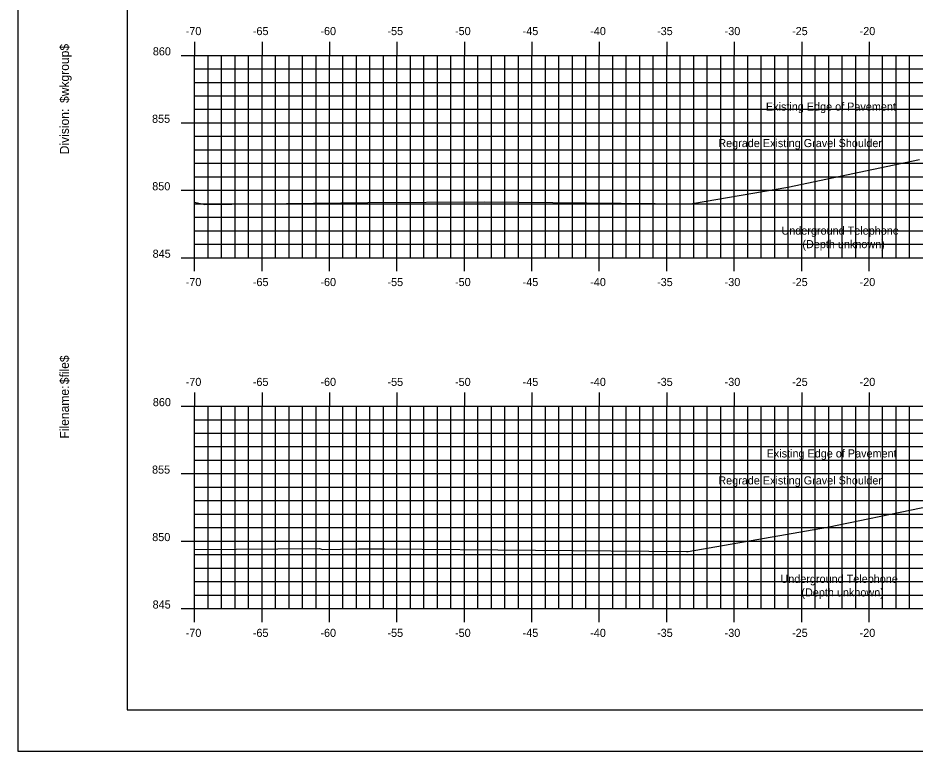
# Model space of a CAD drawing. Extents: x 2193811 to 2194294, y 863888 to 863998.
# Drawn here: x 2193950.1 to 2194016.6, y 863888.4 to 863942.7 of the extents above; entities that cross this region are included whole.
import ezdxf

# ---------------------------------------------------------------- set-up
doc = ezdxf.new("R2010")
doc.units = 0
for name, color, linetype in [('ANNOTATION', 7, 'Continuous'), ('BORDER', 7, 'Continuous'), ('H_V ANNOTATION', 7, 'Continuous'), ('MAJOR', 7, 'Continuous'), ('MINOR', 7, 'Continuous'), ('PLOT BOUNDARY', 7, 'Continuous'), ('S_Roadway_Centerline', 7, 'Continuous')]:
    doc.layers.add(name, color=color, linetype=linetype)

msp = doc.modelspace()

# ---------------------------------------------------------------- linework, layer by layer
at = {"layer": 'BORDER'}
msp.add_lwpolyline([(2193958.23, 863891.446), (2194118.23, 863891.446), (2194118.23, 863996.446), (2193958.23, 863996.446)], close=True, dxfattribs=at)
at = {"layer": 'MAJOR'}
for p, q in [((2193963.23, 863940.948), (2193963.23, 863939.946)), ((2193968.23, 863940.948), (2193968.23, 863939.946)), ((2193973.23, 863940.948), (2193973.23, 863939.946)), ((2193978.23, 863940.948), (2193978.23, 863939.946)), ((2193983.23, 863940.948), (2193983.23, 863939.946)), ((2193988.23, 863940.948), (2193988.23, 863939.946)), ((2193993.23, 863940.948), (2193993.23, 863939.946)), ((2193998.23, 863940.948), (2193998.23, 863939.946)), ((2194003.23, 863940.948), (2194003.23, 863939.946)), ((2194008.23, 863940.948), (2194008.23, 863939.946)), ((2194013.23, 863940.948), (2194013.23, 863939.946)), ((2193962.228, 863939.946), (2193963.23, 863939.946)), ((2193963.23, 863939.946), (2194103.23, 863939.946)), ((2193963.23, 863939.946), (2194103.23, 863939.946)), ((2193963.23, 863924.946), (2193963.23, 863939.946)), ((2193963.23, 863924.946), (2193963.23, 863939.946)), ((2193968.23, 863924.946), (2193968.23, 863939.946)), ((2193973.23, 863924.946), (2193973.23, 863939.946)), ((2193978.23, 863924.946), (2193978.23, 863939.946)), ((2193983.23, 863924.946), (2193983.23, 863939.946)), ((2193988.23, 863924.946), (2193988.23, 863939.946)), ((2193993.23, 863924.946), (2193993.23, 863939.946)), ((2193998.23, 863924.946), (2193998.23, 863939.946)), ((2194003.23, 863924.946), (2194003.23, 863939.946)), ((2194008.23, 863924.946), (2194008.23, 863939.946)), ((2194013.23, 863924.946), (2194013.23, 863939.946)), ((2193962.228, 863934.946), (2193963.23, 863934.946)), ((2193963.23, 863934.946), (2194103.23, 863934.946)), ((2193962.228, 863929.946), (2193963.23, 863929.946)), ((2193963.23, 863929.946), (2194103.23, 863929.946)), ((2193962.228, 863924.946), (2193963.23, 863924.946)), ((2193963.23, 863924.946), (2194103.23, 863924.946)), ((2193963.23, 863923.944), (2193963.23, 863924.946)), ((2193968.23, 863923.944), (2193968.23, 863924.946)), ((2193973.23, 863923.944), (2193973.23, 863924.946)), ((2193978.23, 863923.944), (2193978.23, 863924.946)), ((2193983.23, 863923.944), (2193983.23, 863924.946)), ((2193988.23, 863923.944), (2193988.23, 863924.946)), ((2193993.23, 863923.944), (2193993.23, 863924.946)), ((2193998.23, 863923.944), (2193998.23, 863924.946)), ((2194003.23, 863923.944), (2194003.23, 863924.946)), ((2194008.23, 863923.944), (2194008.23, 863924.946)), ((2194013.23, 863923.944), (2194013.23, 863924.946)), ((2193963.23, 863914.948), (2193963.23, 863913.946)), ((2193968.23, 863914.948), (2193968.23, 863913.946)), ((2193973.23, 863914.948), (2193973.23, 863913.946)), ((2193978.23, 863914.948), (2193978.23, 863913.946)), ((2193983.23, 863914.948), (2193983.23, 863913.946)), ((2193988.23, 863914.948), (2193988.23, 863913.946)), ((2193993.23, 863914.948), (2193993.23, 863913.946)), ((2193998.23, 863914.948), (2193998.23, 863913.946)), ((2194003.23, 863914.948), (2194003.23, 863913.946)), ((2194008.23, 863914.948), (2194008.23, 863913.946)), ((2194013.23, 863914.948), (2194013.23, 863913.946)), ((2193962.228, 863913.946), (2193963.23, 863913.946)), ((2193963.23, 863913.946), (2194103.23, 863913.946)), ((2193963.23, 863913.946), (2194103.23, 863913.946)), ((2193963.23, 863898.946), (2193963.23, 863913.946)), ((2193963.23, 863898.946), (2193963.23, 863913.946)), ((2193968.23, 863898.946), (2193968.23, 863913.946)), ((2193973.23, 863898.946), (2193973.23, 863913.946)), ((2193978.23, 863898.946), (2193978.23, 863913.946)), ((2193983.23, 863898.946), (2193983.23, 863913.946)), ((2193988.23, 863898.946), (2193988.23, 863913.946)), ((2193993.23, 863898.946), (2193993.23, 863913.946)), ((2193998.23, 863898.946), (2193998.23, 863913.946)), ((2194003.23, 863898.946), (2194003.23, 863913.946)), ((2194008.23, 863898.946), (2194008.23, 863913.946)), ((2194013.23, 863898.946), (2194013.23, 863913.946)), ((2193962.228, 863908.946), (2193963.23, 863908.946)), ((2193963.23, 863908.946), (2194103.23, 863908.946)), ((2193962.228, 863903.946), (2193963.23, 863903.946)), ((2193963.23, 863903.946), (2194103.23, 863903.946)), ((2193962.228, 863898.946), (2193963.23, 863898.946)), ((2193963.23, 863898.946), (2194103.23, 863898.946)), ((2193963.23, 863897.944), (2193963.23, 863898.946)), ((2193968.23, 863897.944), (2193968.23, 863898.946)), ((2193973.23, 863897.944), (2193973.23, 863898.946)), ((2193978.23, 863897.944), (2193978.23, 863898.946)), ((2193983.23, 863897.944), (2193983.23, 863898.946)), ((2193988.23, 863897.944), (2193988.23, 863898.946)), ((2193993.23, 863897.944), (2193993.23, 863898.946)), ((2193998.23, 863897.944), (2193998.23, 863898.946)), ((2194003.23, 863897.944), (2194003.23, 863898.946)), ((2194008.23, 863897.944), (2194008.23, 863898.946)), ((2194013.23, 863897.944), (2194013.23, 863898.946))]:
    msp.add_line(p, q, dxfattribs=at)
at = {"layer": 'MINOR'}
for p, q in [((2193964.23, 863924.946), (2193964.23, 863939.946)), ((2193965.23, 863924.946), (2193965.23, 863939.946)), ((2193966.23, 863924.946), (2193966.23, 863939.946)), ((2193967.23, 863924.946), (2193967.23, 863939.946)), ((2193969.23, 863924.946), (2193969.23, 863939.946)), ((2193970.23, 863924.946), (2193970.23, 863939.946)), ((2193971.23, 863924.946), (2193971.23, 863939.946)), ((2193972.23, 863924.946), (2193972.23, 863939.946)), ((2193974.23, 863924.946), (2193974.23, 863939.946)), ((2193975.23, 863924.946), (2193975.23, 863939.946)), ((2193976.23, 863924.946), (2193976.23, 863939.946)), ((2193977.23, 863924.946), (2193977.23, 863939.946)), ((2193979.23, 863924.946), (2193979.23, 863939.946)), ((2193980.23, 863924.946), (2193980.23, 863939.946)), ((2193981.23, 863924.946), (2193981.23, 863939.946)), ((2193982.23, 863924.946), (2193982.23, 863939.946)), ((2193984.23, 863924.946), (2193984.23, 863939.946)), ((2193985.23, 863924.946), (2193985.23, 863939.946)), ((2193986.23, 863924.946), (2193986.23, 863939.946)), ((2193987.23, 863924.946), (2193987.23, 863939.946)), ((2193989.23, 863924.946), (2193989.23, 863939.946)), ((2193990.23, 863924.946), (2193990.23, 863939.946)), ((2193991.23, 863924.946), (2193991.23, 863939.946)), ((2193992.23, 863924.946), (2193992.23, 863939.946)), ((2193994.23, 863924.946), (2193994.23, 863939.946)), ((2193995.23, 863924.946), (2193995.23, 863939.946)), ((2193996.23, 863924.946), (2193996.23, 863939.946)), ((2193997.23, 863924.946), (2193997.23, 863939.946)), ((2193999.23, 863924.946), (2193999.23, 863939.946)), ((2194000.23, 863924.946), (2194000.23, 863939.946)), ((2194001.23, 863924.946), (2194001.23, 863939.946)), ((2194002.23, 863924.946), (2194002.23, 863939.946)), ((2194004.23, 863924.946), (2194004.23, 863939.946)), ((2194005.23, 863924.946), (2194005.23, 863939.946)), ((2194006.23, 863924.946), (2194006.23, 863939.946)), ((2194007.23, 863924.946), (2194007.23, 863939.946)), ((2194009.23, 863924.946), (2194009.23, 863939.946)), ((2194010.23, 863924.946), (2194010.23, 863939.946)), ((2194011.23, 863924.946), (2194011.23, 863939.946)), ((2194012.23, 863924.946), (2194012.23, 863939.946)), ((2194014.23, 863924.946), (2194014.23, 863939.946)), ((2194015.23, 863924.946), (2194015.23, 863939.946)), ((2194016.23, 863924.946), (2194016.23, 863939.946)), ((2193963.23, 863938.946), (2194103.23, 863938.946)), ((2193963.23, 863938.946), (2193964.232, 863938.946)), ((2193963.23, 863937.946), (2194103.23, 863937.946)), ((2193963.23, 863937.946), (2193964.232, 863937.946)), ((2193963.23, 863936.946), (2194103.23, 863936.946)), ((2193963.23, 863936.946), (2193964.232, 863936.946)), ((2193963.23, 863935.946), (2194103.23, 863935.946)), ((2193963.23, 863935.946), (2193964.232, 863935.946)), ((2193963.23, 863933.946), (2194103.23, 863933.946)), ((2193963.23, 863933.946), (2193964.232, 863933.946)), ((2193963.23, 863932.946), (2194103.23, 863932.946)), ((2193963.23, 863932.946), (2193964.232, 863932.946)), ((2193963.23, 863931.946), (2194103.23, 863931.946)), ((2193963.23, 863931.946), (2193964.232, 863931.946)), ((2193963.23, 863930.946), (2194103.23, 863930.946)), ((2193963.23, 863930.946), (2193964.232, 863930.946)), ((2193963.23, 863928.946), (2194103.23, 863928.946)), ((2193963.23, 863928.946), (2193964.232, 863928.946)), ((2193963.23, 863927.946), (2194103.23, 863927.946)), ((2193963.23, 863927.946), (2193964.232, 863927.946)), ((2193963.23, 863926.946), (2194103.23, 863926.946)), ((2193963.23, 863926.946), (2193964.232, 863926.946)), ((2193963.23, 863925.946), (2194103.23, 863925.946)), ((2193963.23, 863925.946), (2193964.232, 863925.946)), ((2193964.23, 863898.946), (2193964.23, 863913.946)), ((2193965.23, 863898.946), (2193965.23, 863913.946)), ((2193966.23, 863898.946), (2193966.23, 863913.946)), ((2193967.23, 863898.946), (2193967.23, 863913.946)), ((2193969.23, 863898.946), (2193969.23, 863913.946)), ((2193970.23, 863898.946), (2193970.23, 863913.946)), ((2193971.23, 863898.946), (2193971.23, 863913.946)), ((2193972.23, 863898.946), (2193972.23, 863913.946)), ((2193974.23, 863898.946), (2193974.23, 863913.946)), ((2193975.23, 863898.946), (2193975.23, 863913.946)), ((2193976.23, 863898.946), (2193976.23, 863913.946)), ((2193977.23, 863898.946), (2193977.23, 863913.946)), ((2193979.23, 863898.946), (2193979.23, 863913.946)), ((2193980.23, 863898.946), (2193980.23, 863913.946)), ((2193981.23, 863898.946), (2193981.23, 863913.946)), ((2193982.23, 863898.946), (2193982.23, 863913.946)), ((2193984.23, 863898.946), (2193984.23, 863913.946)), ((2193985.23, 863898.946), (2193985.23, 863913.946)), ((2193986.23, 863898.946), (2193986.23, 863913.946)), ((2193987.23, 863898.946), (2193987.23, 863913.946)), ((2193989.23, 863898.946), (2193989.23, 863913.946)), ((2193990.23, 863898.946), (2193990.23, 863913.946)), ((2193991.23, 863898.946), (2193991.23, 863913.946)), ((2193992.23, 863898.946), (2193992.23, 863913.946)), ((2193994.23, 863898.946), (2193994.23, 863913.946)), ((2193995.23, 863898.946), (2193995.23, 863913.946)), ((2193996.23, 863898.946), (2193996.23, 863913.946)), ((2193997.23, 863898.946), (2193997.23, 863913.946)), ((2193999.23, 863898.946), (2193999.23, 863913.946)), ((2194000.23, 863898.946), (2194000.23, 863913.946)), ((2194001.23, 863898.946), (2194001.23, 863913.946)), ((2194002.23, 863898.946), (2194002.23, 863913.946)), ((2194004.23, 863898.946), (2194004.23, 863913.946)), ((2194005.23, 863898.946), (2194005.23, 863913.946)), ((2194006.23, 863898.946), (2194006.23, 863913.946)), ((2194007.23, 863898.946), (2194007.23, 863913.946)), ((2194009.23, 863898.946), (2194009.23, 863913.946)), ((2194010.23, 863898.946), (2194010.23, 863913.946)), ((2194011.23, 863898.946), (2194011.23, 863913.946)), ((2194012.23, 863898.946), (2194012.23, 863913.946)), ((2194014.23, 863898.946), (2194014.23, 863913.946)), ((2194015.23, 863898.946), (2194015.23, 863913.946)), ((2194016.23, 863898.946), (2194016.23, 863913.946)), ((2193963.23, 863912.946), (2194103.23, 863912.946)), ((2193963.23, 863912.946), (2193964.232, 863912.946)), ((2193963.23, 863911.946), (2194103.23, 863911.946)), ((2193963.23, 863911.946), (2193964.232, 863911.946)), ((2193963.23, 863910.946), (2194103.23, 863910.946)), ((2193963.23, 863910.946), (2193964.232, 863910.946)), ((2193963.23, 863909.946), (2194103.23, 863909.946)), ((2193963.23, 863909.946), (2193964.232, 863909.946)), ((2193963.23, 863907.946), (2194103.23, 863907.946)), ((2193963.23, 863907.946), (2193964.232, 863907.946)), ((2193963.23, 863906.946), (2194103.23, 863906.946)), ((2193963.23, 863906.946), (2193964.232, 863906.946)), ((2193963.23, 863905.946), (2194103.23, 863905.946)), ((2193963.23, 863905.946), (2193964.232, 863905.946)), ((2193963.23, 863904.946), (2194103.23, 863904.946)), ((2193963.23, 863904.946), (2193964.232, 863904.946)), ((2193963.23, 863902.946), (2194103.23, 863902.946)), ((2193963.23, 863902.946), (2193964.232, 863902.946)), ((2193963.23, 863901.946), (2194103.23, 863901.946)), ((2193963.23, 863901.946), (2193964.232, 863901.946)), ((2193963.23, 863900.946), (2194103.23, 863900.946)), ((2193963.23, 863900.946), (2193964.232, 863900.946)), ((2193963.23, 863899.946), (2194103.23, 863899.946)), ((2193963.23, 863899.946), (2193964.232, 863899.946))]:
    msp.add_line(p, q, dxfattribs=at)
at = {"layer": 'PLOT BOUNDARY'}
msp.add_lwpolyline([(2193950.137, 863888.387), (2194120.137, 863888.387), (2194120.137, 863998.387), (2193950.137, 863998.387)], close=True, dxfattribs=at)
at = {"layer": 'S_Roadway_Centerline'}
for points in [[(2193963.23, 863929.076), (2193963.995, 863928.9), (2193976.06, 863929.037), (2193984.755, 863929.09), (2193999.882, 863928.954), (2194000.145, 863928.967), (2194007.204, 863930.189), (2194016.97, 863932.216)], [(2193963.23, 863903.335), (2193972.487, 863903.387), (2193972.709, 863903.336), (2193975.387, 863903.366), (2193977.316, 863903.378), (2193999.693, 863903.176), (2193999.824, 863903.182), (2194010.154, 863904.971), (2194017.091, 863906.411), (2194018.437, 863906.546), (2194019.884, 863906.782), (2194020.782, 863906.873)]]:
    msp.add_lwpolyline(points, dxfattribs=at)

# ---------------------------------------------------------------- texts
at = {"layer": 'ANNOTATION'}
for s, p in [('Existing Edge of Pavement', (2194005.579, 863935.848)), ('Regrade Existing Gravel Shoulder', (2194002.048, 863933.146)), ('Underground Telephone', (2194006.73, 863926.658)), ('(Depth unknown)', (2194008.28, 863925.656)), ('Existing Edge of Pavement', (2194005.63, 863910.146)), ('Regrade Existing Gravel Shoulder', (2194002.048, 863908.146)), ('Underground Telephone', (2194006.656, 863900.848)), ('(Depth unknown)', (2194008.206, 863899.846))]:
    msp.add_text(s, height=0.6, dxfattribs=at).set_placement(p)
at = {"layer": 'BORDER'}
for s, p in [('$wkgroup$', (2193953.915, 863936.415)), ('Division:', (2193953.915, 863932.612)), ('$file$', (2193953.915, 863915.571)), ('Filename:', (2193953.915, 863911.544))]:
    msp.add_text(s, height=0.6696, rotation=90, dxfattribs=at).set_placement(p)
at = {"layer": 'H_V ANNOTATION'}
for s, p in [('-70', (2193962.571, 863941.446)), ('-65', (2193967.547, 863941.446)), ('-60', (2193972.555, 863941.446)), ('-55', (2193977.526, 863941.446)), ('-50', (2193982.534, 863941.446)), ('-45', (2193987.547, 863941.446)), ('-40', (2193992.555, 863941.446)), ('-35', (2193997.51, 863941.446)), ('-30', (2194002.518, 863941.446)), ('-25', (2194007.515, 863941.446)), ('-20', (2194012.523, 863941.446)), ('860', (2193960.135, 863939.946)), ('855', (2193960.076, 863934.946)), ('850', (2193960.092, 863929.946)), ('845', (2193960.119, 863924.946)), ('-70', (2193962.571, 863922.846)), ('-65', (2193967.547, 863922.846)), ('-60', (2193972.555, 863922.846)), ('-55', (2193977.526, 863922.846)), ('-50', (2193982.534, 863922.846)), ('-45', (2193987.547, 863922.846)), ('-40', (2193992.555, 863922.846)), ('-35', (2193997.51, 863922.846)), ('-30', (2194002.518, 863922.846)), ('-25', (2194007.515, 863922.846)), ('-20', (2194012.523, 863922.846)), ('-70', (2193962.571, 863915.446)), ('-65', (2193967.547, 863915.446)), ('-60', (2193972.555, 863915.446)), ('-55', (2193977.526, 863915.446)), ('-50', (2193982.534, 863915.446)), ('-45', (2193987.547, 863915.446)), ('-40', (2193992.555, 863915.446)), ('-35', (2193997.51, 863915.446)), ('-30', (2194002.518, 863915.446)), ('-25', (2194007.515, 863915.446)), ('-20', (2194012.523, 863915.446)), ('860', (2193960.135, 863913.946)), ('855', (2193960.076, 863908.946)), ('850', (2193960.092, 863903.946)), ('845', (2193960.119, 863898.946)), ('-70', (2193962.571, 863896.846)), ('-65', (2193967.547, 863896.846)), ('-60', (2193972.555, 863896.846)), ('-55', (2193977.526, 863896.846)), ('-50', (2193982.534, 863896.846)), ('-45', (2193987.547, 863896.846)), ('-40', (2193992.555, 863896.846)), ('-35', (2193997.51, 863896.846)), ('-30', (2194002.518, 863896.846)), ('-25', (2194007.515, 863896.846)), ('-20', (2194012.523, 863896.846))]:
    msp.add_text(s, height=0.6, dxfattribs=at).set_placement(p)

doc.saveas('drawing.dxf')
